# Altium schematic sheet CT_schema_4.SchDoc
size 396 x 205 mm
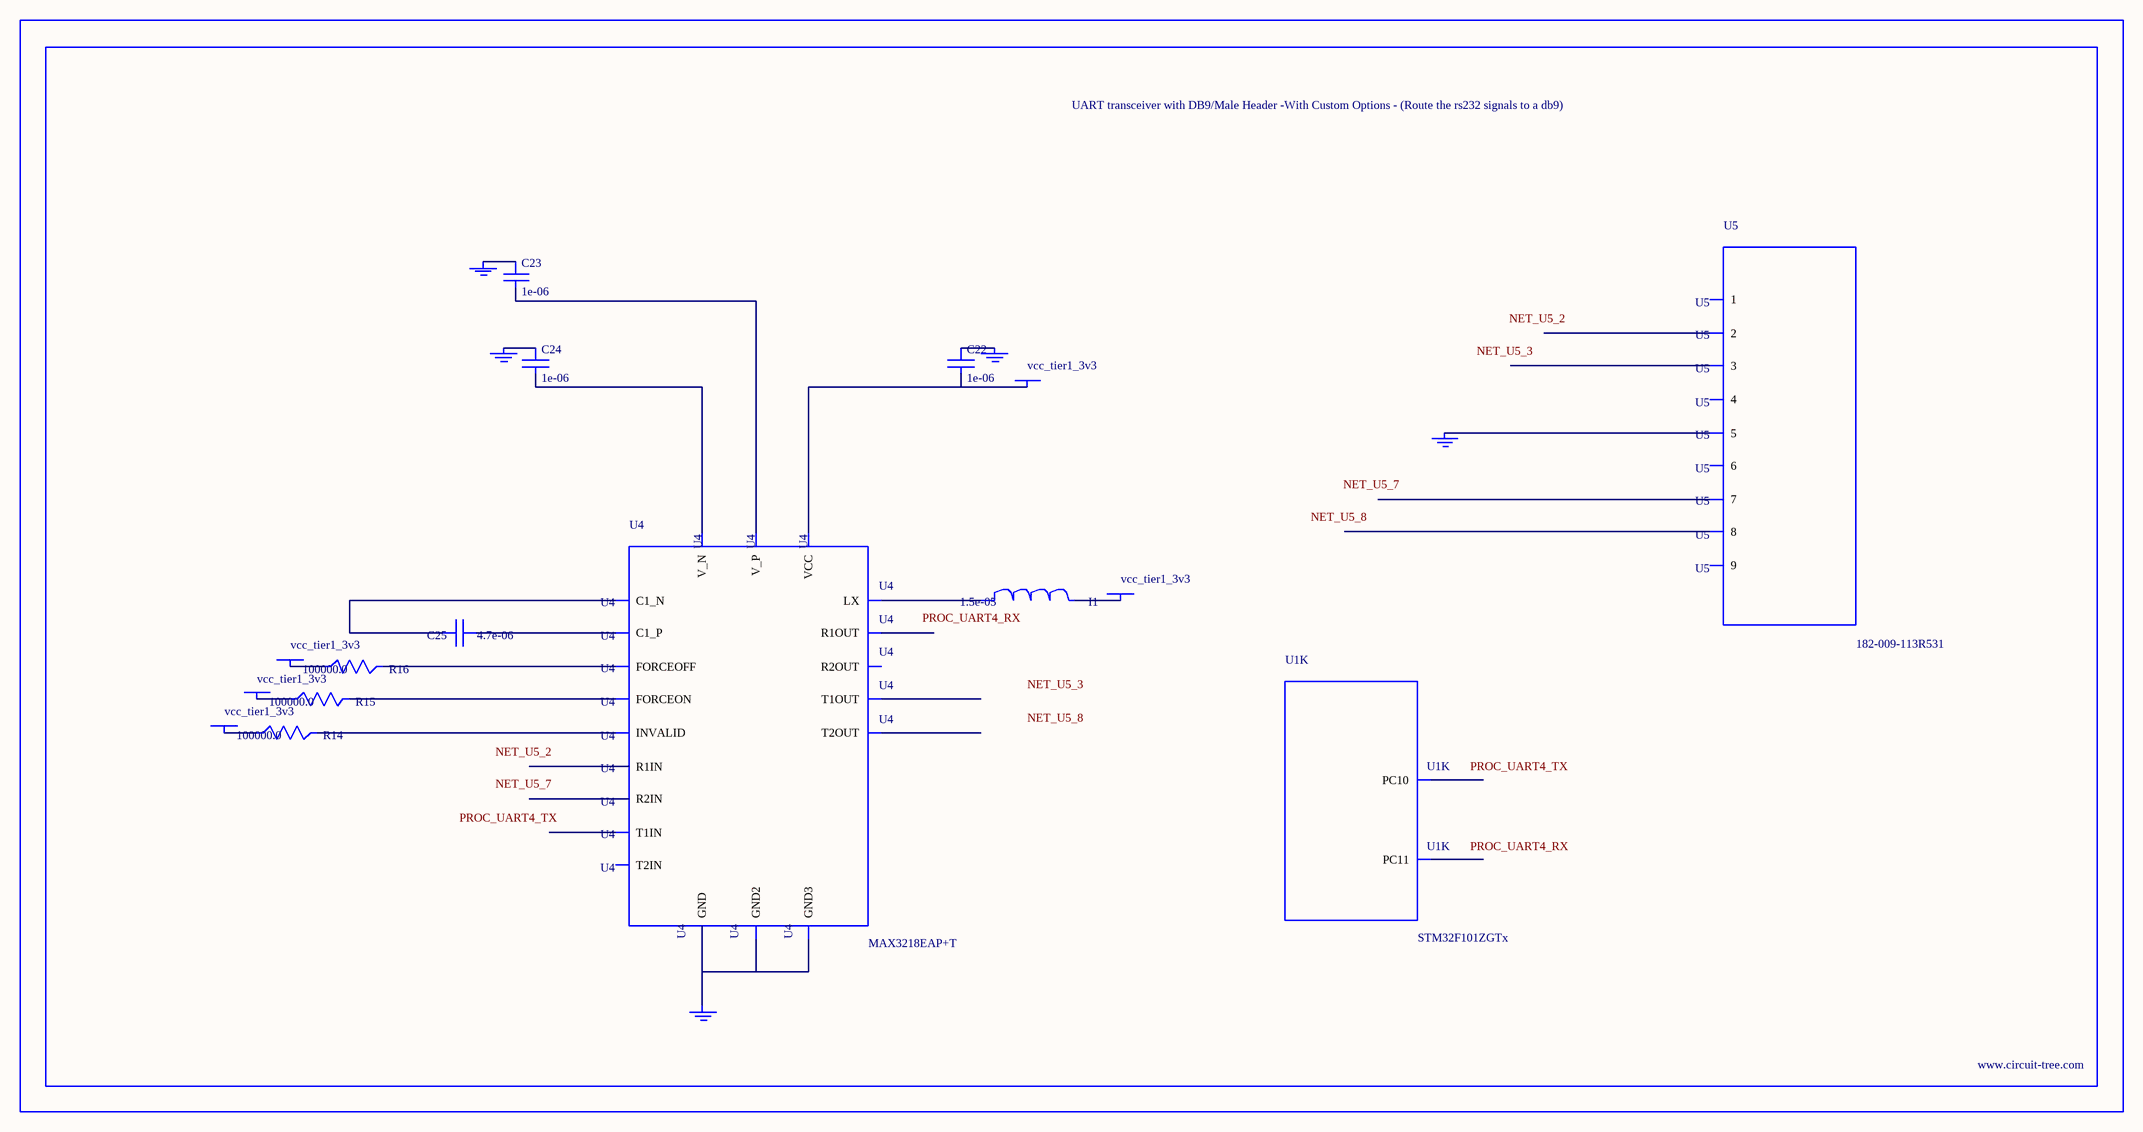
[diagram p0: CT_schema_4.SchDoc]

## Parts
BORDER3  (no value)
C22  1e-06  [C0603]
C23  1e-06  [C0603]
C24  1e-06  [C0603]
C25  4.7e-06  [C0805]
GND_INSTANCE_3_0  (no value)
GND_INSTANCE_3_1  (no value)
GND_INSTANCE_3_2  (no value)
GND_INSTANCE_3_3  (no value)
GND_INSTANCE_3_4  (no value)
I1  1.5e-05  [L1210]
POWER_INSTANCE_3_0  vcc_tier1_3v3
POWER_INSTANCE_3_1  vcc_tier1_3v3
POWER_INSTANCE_3_2  vcc_tier1_3v3
POWER_INSTANCE_3_3  vcc_tier1_3v3
POWER_INSTANCE_3_4  vcc_tier1_3v3
R14  100000.0  [R0603]
R15  100000.0  [R0603]
R16  100000.0  [R0603]
U1  STM32F101ZGTx  [LQFP144]  (part K of 13)
U4  MAX3218EAP+T  [SSOP-20]
U5  182-009-113R531  [182-009-MALE]

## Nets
NetC22_1: C22.1 GND_INSTANCE_3_0.0(GND)
NetC22_2: C22.2 POWER_INSTANCE_3_4.0(PWR) U4.6(VCC)
NetC23_1: C23.1 GND_INSTANCE_3_2.0(GND)
NetC23_2: C23.2 U4.19(V_P)
NetC24_1: C24.1 GND_INSTANCE_3_1.0(GND)
NetC24_2: C24.2 U4.15(V_N)
NetC25_1: C25.1 U4.18(C1_P)
NetC25_2: C25.2 U4.16(C1_N)
NetGND_INSTANCE_3_3_0: GND_INSTANCE_3_3.0(GND) U4.5(GND) U4.17(GND2) U4.20(GND3)
NetGND_INSTANCE_3_4_0: GND_INSTANCE_3_4.0(GND) U5.5
NetI1_1: I1.1 U4.1(LX)
NetI1_2: I1.2 POWER_INSTANCE_3_0.0(PWR)
NetPOWER_INSTANCE_3_1_0: POWER_INSTANCE_3_1.0(PWR) R14.1
NetPOWER_INSTANCE_3_2_0: POWER_INSTANCE_3_2.0(PWR) R15.1
NetPOWER_INSTANCE_3_3_0: POWER_INSTANCE_3_3.0(PWR) R16.1
NetR14_2: R14.2 U4.2(INVALID)
NetR15_2: R15.2 U4.3(FORCEON)
NetR16_2: R16.2 U4.4(FORCEOFF)

Not connected (* = marked no-connect by the designer): U1 111(PC10) 112(PC11); U4 7(T1IN) 8(T2IN) 9(R1OUT) 10(R2OUT) 11(R2IN) 12(R1IN) 13(T2OUT) 14(T1OUT); U5 1 2 3 4 6 7 8 9

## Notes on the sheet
- Labels drawn without touching a wire or pin: NET_U5_2, NET_U5_3, NET_U5_7, NET_U5_8, PROC_UART4_RX, PROC_UART4_TX

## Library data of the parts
BORDER3 = BORDER_PAGE3
C22-C24 = C0603C105K3RACTU
C25 = C0805C475K4RACTU
GND_INSTANCE_3_0-GND_INSTANCE_3_4 = GND
I1 = L1210R150MDWIT
POWER_INSTANCE_3_0-POWER_INSTANCE_3_4 = PWR
R14-R16 = RC0603JR-07100KL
